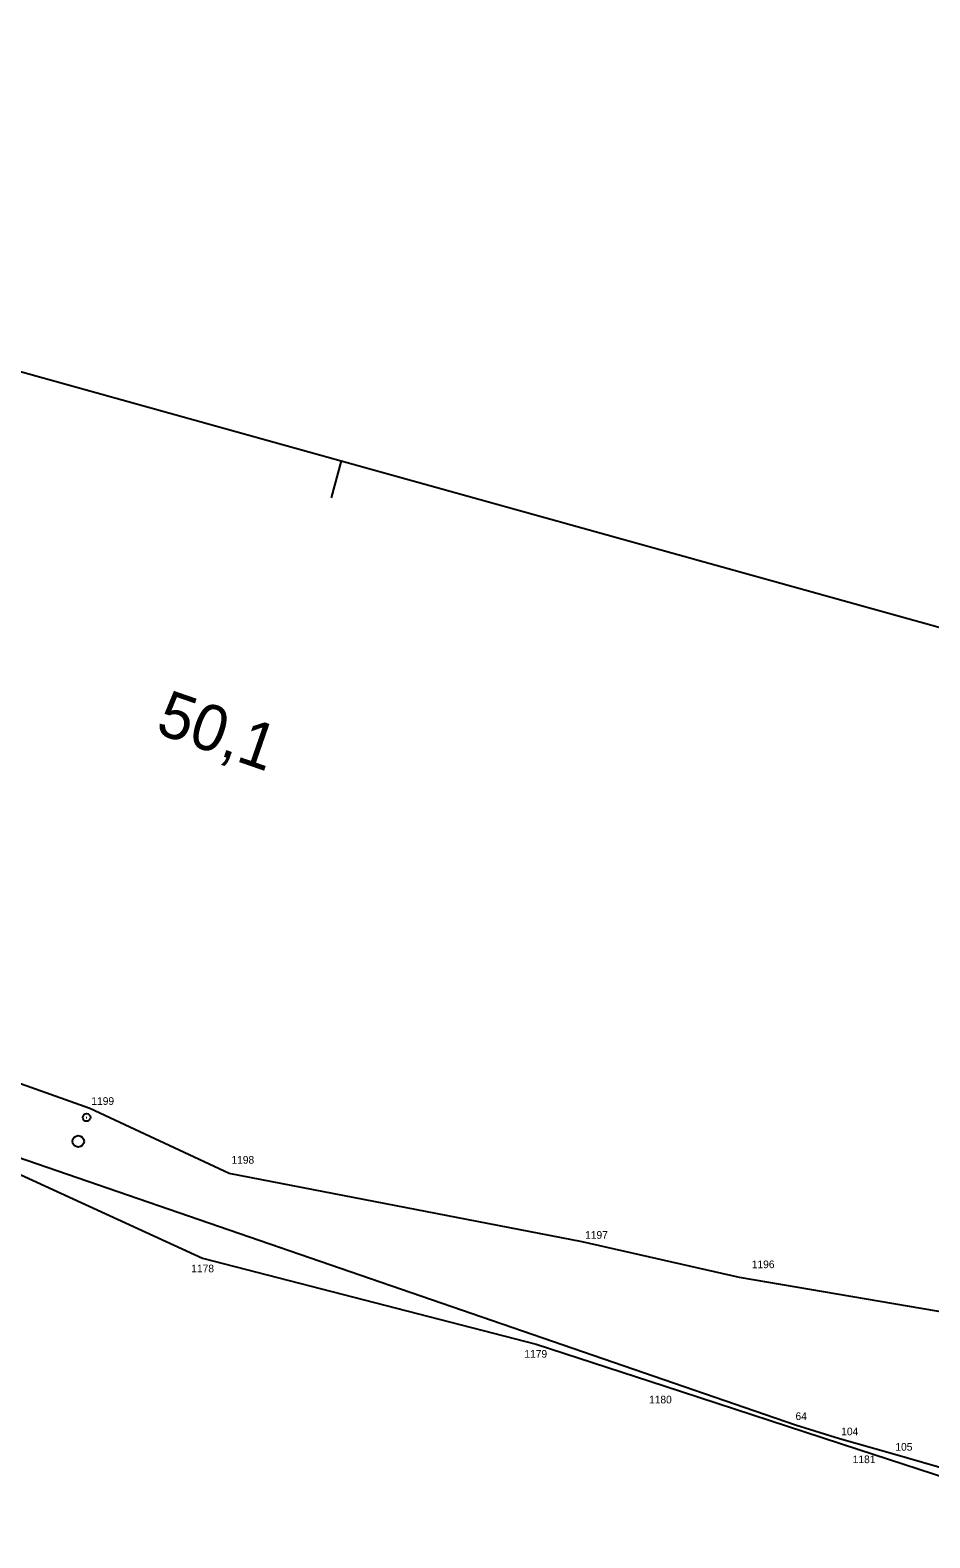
# Model space of a CAD drawing. Extents: x -678084 to -677195, y -1006706 to -1006195.
# Drawn here: x -677640.8 to -677523.2, y -1006447.9 to -1006250.8 of the extents above; entities that cross this region are included whole.
import ezdxf

# ---------------------------------------------------------------- set-up
doc = ezdxf.new("R2010")
doc.units = 0
for name, color, linetype in [('rozpiska - rámy', 7, 'Continuous'), ('SSZT nové - lomové body', 7, 'Continuous'), ('SSZT_nové', 7, 'Continuous'), ('SŽDC', 7, 'Continuous'), ('SŽDC - body', 7, 'Continuous'), ('Vrstva 7', 7, 'Continuous')]:
    doc.layers.add(name, color=color, linetype=linetype)

msp = doc.modelspace()

# ---------------------------------------------------------------- linework, layer by layer
at = {"layer": 'rozpiska - rámy'}
for p, q in [((-677802.41, -1006250.83), (-677600.1, -1006307.13)), ((-677600.1, -1006307.13), (-677601.44, -1006311.95)), ((-677600.1, -1006307.13), (-677397.78, -1006363.43))]:
    msp.add_line(p, q, dxfattribs=at)
at = {"layer": 'SSZT nové - lomové body'}
for p, q in [((-677540.71, -1006433.07), (-677540.71, -1006433.07)), ((-677534.99, -1006434.85), (-677534.99, -1006434.85)), ((-677528.03, -1006436.83), (-677528.03, -1006436.83))]:
    msp.add_line(p, q, dxfattribs=at)
at = {"layer": 'SSZT_nové'}
for points in [[(-678046.18, -1006343.51), (-678039.76, -1006343.69), (-678028.1, -1006343.37), (-677988.11, -1006347.69), (-677946.88, -1006353.16), (-677896.95, -1006358.97), (-677855.43, -1006364.26), (-677800.81, -1006372.62), (-677763.07, -1006378.4), (-677730.99, -1006381.64), (-677703.96, -1006383), (-677678.22, -1006388.09), (-677650.5, -1006395.33), (-677540.71, -1006433.07)], [(-677540.71, -1006433.07), (-677534.99, -1006434.85), (-677528.03, -1006436.83), (-677520.22, -1006439.09), (-677512.96, -1006440.72), (-677505.14, -1006443.41), (-677489.54, -1006444.26)]]:
    msp.add_lwpolyline(points, dxfattribs=at)
at = {"layer": 'SŽDC'}
for p, q in [((-677632.95, -1006391.74), (-677656.86, -1006383.31)), ((-677614.75, -1006400.23), (-677632.95, -1006391.74)), ((-677647.54, -1006397.88), (-677618.24, -1006411.32)), ((-677568.61, -1006409.18), (-677614.75, -1006400.23)), ((-677548.06, -1006413.85), (-677568.61, -1006409.18)), ((-677618.24, -1006411.32), (-677574.61, -1006422.53)), ((-677505.74, -1006421.01), (-677548.06, -1006413.85)), ((-677574.61, -1006422.53), (-677557.88, -1006428)), ((-677557.88, -1006428), (-677532.59, -1006436.26)), ((-677532.59, -1006436.26), (-677497.11, -1006447.85))]:
    msp.add_line(p, q, dxfattribs=at)
at = {"layer": 'SŽDC - body'}
for p, q in [((-677632.95, -1006391.74), (-677632.95, -1006391.74)), ((-677614.75, -1006400.23), (-677614.75, -1006400.23)), ((-677568.61, -1006409.18), (-677568.61, -1006409.18)), ((-677618.24, -1006411.32), (-677618.24, -1006411.32)), ((-677548.06, -1006413.85), (-677548.06, -1006413.85)), ((-677574.61, -1006422.53), (-677574.61, -1006422.53)), ((-677557.88, -1006428), (-677557.88, -1006428)), ((-677532.59, -1006436.26), (-677532.59, -1006436.26))]:
    msp.add_line(p, q, dxfattribs=at)
at = {"layer": 'Vrstva 7'}
msp.add_line((-677633.44, -1006392.91), (-677633.35, -1006392.94), dxfattribs=at)
for centre, radius in [((-677633.4, -1006392.92), 0.5), ((-677634.48, -1006396.04), 0.75)]:
    msp.add_circle(centre, radius, dxfattribs=at)

# ---------------------------------------------------------------- texts
at = {"layer": 'SSZT nové - lomové body'}
for s, p in [('64', (-677540.72, -1006432.45)), ('104', (-677534.75, -1006434.45)), ('105', (-677527.67, -1006436.46))]:
    msp.add_text(s, height=1, dxfattribs=at).set_placement(p)
at = {"layer": 'SŽDC - body'}
for s, p in [('1199', (-677632.77, -1006391.27)), ('1198', (-677614.46, -1006398.96)), ('1197', (-677568.23, -1006408.77)), ('1178', (-677619.71, -1006413.15)), ('1196', (-677546.44, -1006412.61)), ('1179', (-677576.17, -1006424.31)), ('1180', (-677559.87, -1006430.28)), ('1181', (-677533.25, -1006438.09))]:
    msp.add_text(s, height=1, dxfattribs=at).set_placement(p)
at = {"layer": 'Vrstva 7'}
msp.add_text('50,1', height=6, rotation=340.8846, dxfattribs=at).set_placement((-677624.57, -1006342.62))

doc.saveas('drawing.dxf')
